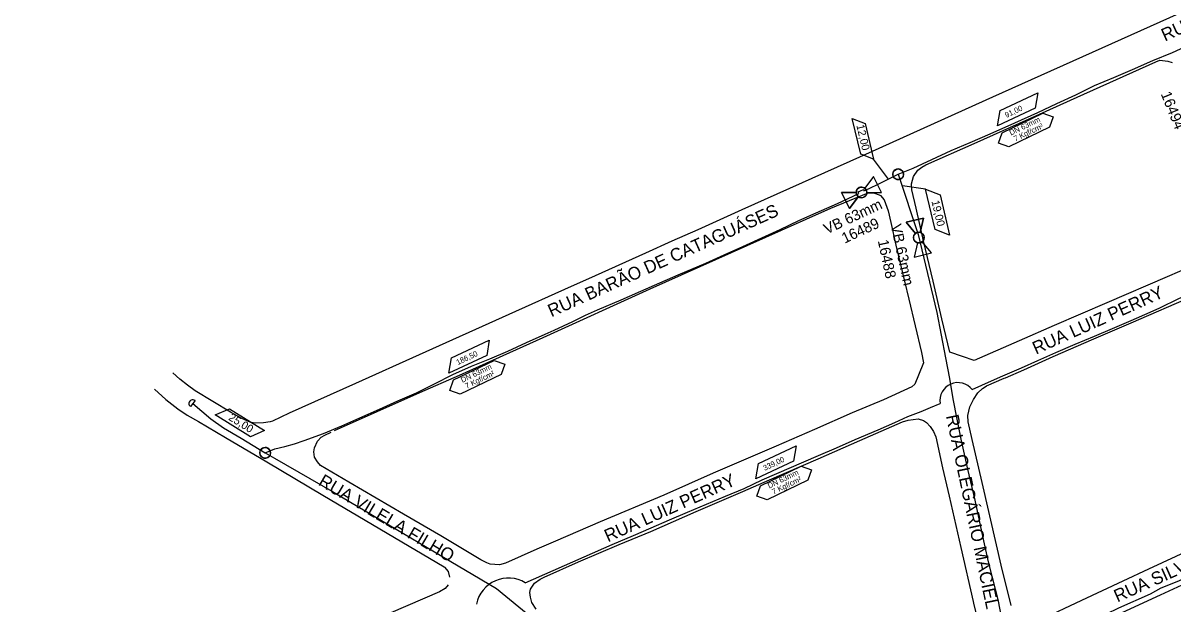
# Model space of a CAD drawing. Extents: x 656692 to 673945, y 7585994 to 7599066.
# Drawn here: x 668346 to 668995, y 7595131 to 7595459 of the extents above; entities that cross this region are included whole.
import ezdxf

# ---------------------------------------------------------------- set-up
doc = ezdxf.new("R2010")
doc.units = 0
for name, color, linetype in [('LOGRADOURO', 7, 'Continuous'), ('LOGRADOURO_TEXTO', 7, 'Continuous'), ('SIMBOLO', 7, 'Continuous'), ('TEXTO', 7, 'Continuous'), ('TUBO_PEAD_GN_63', 7, 'Continuous'), ('VALVULA_PEAD_63', 7, 'Continuous')]:
    doc.layers.add(name, color=color, linetype=linetype)

# ---------------------------------------------------------------- blocks, each defined once
blk = doc.blocks.new('VALVULA_PEAD_DN_16')
at = {"layer": 'VALVULA_PEAD_63'}
for points in [[(-0.0374, 0.0187), (-0.1395, 0.0698), (-0.1395, -0.0698), (-0.0374, -0.0187)], [(-0.0374, -0.0187), (-0.1395, -0.0698), (-0.1395, 0.0698), (-0.0374, 0.0187)], [(0.0374, -0.0187), (0.1395, -0.0698), (0.1395, 0.0698), (0.0374, 0.0187)], [(0.0374, -0.0187), (0.1395, -0.0698), (0.1395, 0.0698), (0.0374, 0.0187)]]:
    blk.add_lwpolyline(points, dxfattribs=at)
blk.add_circle((0, 0), 0.0419, dxfattribs=at)
for start, end in [(90, 270), (153.43495, 206.56505), (270, 90), (333.43495, 26.56505)]:
    blk.add_arc((0, 0), 0.0419, start, end, dxfattribs=at)
blk = doc.blocks.new('INTERLIGACAO_9')
at = {"layer": 'SIMBOLO'}
blk.add_circle((0, 0), 4.19, dxfattribs=at)
for start, end in [(0, 180), (180, 0)]:
    blk.add_arc((0, 0), 4.19, start, end, dxfattribs=at)

msp = doc.modelspace()

# ---------------------------------------------------------------- linework, layer by layer
at = {"layer": 'LOGRADOURO'}
for points in [[(669095.2, 7595507.7), (668966.3, 7595449.79), (668893.69, 7595417.16), (668825.71, 7595386.62), (668752.03, 7595353.68), (668727.27, 7595342.48), (668712.54, 7595335.94), (668697.66, 7595329.3), (668665.49, 7595314.85), (668655.65, 7595310.4), (668620.5, 7595294.72), (668569.88, 7595271.98), (668533.87, 7595255.79), (668496.45, 7595239.02), (668486.96, 7595234.51), (668485.66, 7595234.05), (668481.99, 7595233.54), (668477.36, 7595233.36), (668474.76, 7595233.65), (668469.68, 7595235.96), (668463.28, 7595239.51), (668443.29, 7595251.52), (668439, 7595254.73), (668434.77, 7595258.09), (668430.81, 7595261.82)], [(669013.1, 7595324.83), (668992.3, 7595315.82), (668958.18, 7595301.17), (668928.49, 7595288.41), (668908.71, 7595279.71), (668883.26, 7595268.7), (668876.62, 7595270.96), (668869.59, 7595273.35), (668865.06, 7595292.18), (668860.14, 7595313.52), (668854.66, 7595336.27), (668850.43, 7595354.61), (668848.11, 7595364.89), (668847.92, 7595368.35), (668848.97, 7595372.5), (668851.47, 7595376.04), (668853.69, 7595377.77), (668855.93, 7595379.08), (668883.16, 7595391.12), (668914.22, 7595405.05), (668941.38, 7595417.28), (668985.8, 7595437.14), (668988.02, 7595438.05), (668992.52, 7595437.56), (668995.03, 7595436.8)], [(668829.51, 7595362.24), (668830.43, 7595361.7), (668832.39, 7595359.31), (668834.67, 7595353.16), (668836.23, 7595346.52), (668839.07, 7595333.81), (668846.37, 7595303.29), (668853.42, 7595273.26), (668854.71, 7595267.4), (668851.88, 7595260.5), (668849.76, 7595255.28), (668848.05, 7595253.75), (668832.05, 7595246.5), (668814.39, 7595239.11), (668793.16, 7595229.81), (668771.48, 7595220.34), (668735.79, 7595205.11), (668708.02, 7595192.68), (668672.1, 7595177.61), (668646.92, 7595166.81), (668636.34, 7595162.21), (668618.61, 7595154.32), (668615.17, 7595153.51), (668610.02, 7595153.84), (668608, 7595154.59), (668604.64, 7595156.24), (668582.12, 7595169.71), (668561, 7595182.06), (668530.09, 7595200.09), (668514.15, 7595209.52), (668512.43, 7595211.51), (668510.78, 7595214.1), (668510.36, 7595217.12), (668510.71, 7595219.43), (668512.36, 7595223.22), (668514.5, 7595225.44), (668516.59, 7595226.65), (668520.18, 7595228.24)], [(668802.36, 7595354.63), (668823.4, 7595363.24), (668826.99, 7595363.17), (668829.51, 7595362.24)], [(668522.14, 7595229.12), (668570.28, 7595250.56), (668592.66, 7595260.39), (668639.85, 7595281.68), (668700.36, 7595309.18), (668746.28, 7595329.64), (668774.48, 7595342.15), (668802.36, 7595354.63)], [(668904.06, 7595130.54), (668898.51, 7595153.33), (668895.91, 7595164.68), (668887.82, 7595199.81), (668882.14, 7595224.07), (668879.84, 7595234.13), (668879.7, 7595237.73), (668880.81, 7595242.49), (668882.83, 7595246.73), (668885.29, 7595250.42), (668887.9, 7595252.93), (668889.45, 7595253.87), (668890.18, 7595254.32), (668900.17, 7595258.78), (668901.03, 7595259.01), (668911.32, 7595263.45), (668927.81, 7595270.9), (668950.83, 7595280.89), (668971.82, 7595289.9), (669007.48, 7595305.37)], [(668420.49, 7595252.56), (668426.74, 7595246.74), (668433.65, 7595241.39), (668438.9, 7595237.79), (668445.27, 7595234.25), (668460.45, 7595225.28), (668483.83, 7595211.46), (668515.38, 7595192.72), (668583.94, 7595152.26), (668584.21, 7595152.13), (668586.25, 7595149.68), (668587.01, 7595146.45)], [(668635.95, 7595128.47), (668633.45, 7595132.15), (668632.65, 7595135.22), (668632.27, 7595137.86), (668632.8, 7595139.77), (668635, 7595143.09), (668638.2, 7595145.41), (668640.5, 7595146.52), (668659.83, 7595155.09), (668682.73, 7595164.9), (668700.58, 7595172.24), (668726.33, 7595183.43), (668752.68, 7595194.84), (668767.65, 7595201.45), (668795.24, 7595213.32), (668818.64, 7595223.65), (668842.79, 7595234.13), (668845.93, 7595235.05), (668851.64, 7595235.83), (668854.67, 7595234.87), (668856.4, 7595233.69), (668858.45, 7595231.55), (668860.29, 7595228.62), (668861.53, 7595225.55), (668865.45, 7595208.13), (668869.1, 7595192.21), (668875.78, 7595163.23), (668882.69, 7595132.81), (668882.94, 7595131.72), (668885.16, 7595122.52)], [(669004.76, 7595161.75), (668981.67, 7595150.9), (668967.21, 7595144.22), (668943.82, 7595133.25), (668920.73, 7595122.42)], [(668925.27, 7595107.28), (668988.53, 7595136.48), (669015.31, 7595149)], [(668586.17, 7595142.17), (668584.61, 7595140.11), (668581.34, 7595138.22), (668526.44, 7595114.47), (668496.18, 7595101.48), (668451.14, 7595081.88), (668416.13, 7595066.8), (668395.98, 7595058.02), (668377.86, 7595050.28), (668373.21, 7595049.71), (668368.41, 7595050.52), (668367.4, 7595050.88), (668364.76, 7595052.52), (668361.54, 7595055.64), (668359.18, 7595059.46), (668353.9, 7595071.87), (668346.14, 7595089.62)]]:
    msp.add_lwpolyline(points, dxfattribs=at)
at = {"layer": 'SIMBOLO'}
for points in [[(668896.95, 7595391.28), (668899.02, 7595397.18), (668922.04, 7595408.24), (668927.94, 7595406.17), (668925.87, 7595400.26), (668902.85, 7595389.21), (668896.95, 7595391.28)], [(668587.19, 7595251.82), (668589.26, 7595257.73), (668612.28, 7595268.79), (668618.18, 7595266.71), (668616.11, 7595260.81), (668593.09, 7595249.75), (668587.19, 7595251.82)], [(668760.46, 7595192.16), (668762.53, 7595198.07), (668785.55, 7595209.12), (668791.45, 7595207.05), (668789.38, 7595201.15), (668766.36, 7595190.09), (668760.46, 7595192.16)]]:
    msp.add_lwpolyline(points, dxfattribs=at)
at = {"layer": 'TEXTO'}
for p, q in [((668834.84, 7595371.04), (668826.33, 7595382.3)), ((668855.85, 7595365.33), (668842.73, 7595367.22))]:
    msp.add_line(p, q, dxfattribs=at)
for points in [[(668897.91, 7595409.73), (668919.19, 7595419.7), (668917.78, 7595411.05), (668896.36, 7595401.03), (668897.91, 7595409.73)], [(668897.91, 7595409.73), (668919.19, 7595419.7), (668917.78, 7595411.05), (668896.36, 7595401.03), (668897.91, 7595409.73)], [(668821.63, 7595402.35), (668826.33, 7595382.3), (668819.17, 7595385.07), (668814.44, 7595405.24), (668821.63, 7595402.35)], [(668863.96, 7595362.07), (668869.26, 7595339.45), (668861.19, 7595342.58), (668855.85, 7595365.34), (668863.96, 7595362.07)], [(668863.96, 7595362.07), (668869.26, 7595339.45), (668861.19, 7595342.58), (668855.85, 7595365.33), (668863.96, 7595362.07)], [(668588.15, 7595270.28), (668609.43, 7595280.25), (668608.02, 7595271.6), (668586.6, 7595261.57), (668588.15, 7595270.28)], [(668588.15, 7595270.28), (668609.44, 7595280.25), (668608.02, 7595271.6), (668586.61, 7595261.57), (668588.15, 7595270.28)], [(668462.76, 7595241.39), (668482.5, 7595229.15), (668474.58, 7595225.65), (668454.72, 7595237.97), (668462.76, 7595241.39)], [(668462.76, 7595241.39), (668482.5, 7595229.15), (668474.58, 7595225.65), (668454.72, 7595237.96), (668462.76, 7595241.39)], [(668761.41, 7595210.62), (668782.7, 7595220.58), (668781.29, 7595211.94), (668759.87, 7595201.91), (668761.41, 7595210.62)], [(668761.42, 7595210.62), (668782.7, 7595220.58), (668781.29, 7595211.94), (668759.87, 7595201.91), (668761.42, 7595210.62)]]:
    msp.add_lwpolyline(points, dxfattribs=at)
at = {"layer": 'TUBO_PEAD_GN_63'}
msp.add_line((668443.28, 7595246.12), (668440.69, 7595242.71), dxfattribs=at)
for points in [[(668840.32, 7595373.73), (668840.36, 7595373.75), (668848.75, 7595377.25), (668859.32, 7595382.09), (668870.21, 7595387.08), (668880.98, 7595391.75), (668892.22, 7595396.65), (668906.3, 7595402.81), (668919.21, 7595408.53), (668929.89, 7595413.58), (668940.66, 7595418.62), (668951.23, 7595423.75), (668962.11, 7595428.32), (668972.67, 7595432.89), (668984.21, 7595437.92), (668995.22, 7595442.46), (669004.26, 7595446.49)], [(668819.12, 7595364.38), (668820.75, 7595365.07), (668821.02, 7595364.48), (668823.92, 7595365.81), (668829.36, 7595368.35), (668840.32, 7595373.73)], [(668840.36, 7595373.75), (668851.55, 7595339.81), (668862.24, 7595295.86), (668867.06, 7595270.12), (668869.3, 7595258.61), (668871.25, 7595247.01), (668873.42, 7595235.62), (668875.64, 7595224.28), (668879.52, 7595207.33), (668883.53, 7595189.9), (668885.99, 7595178.53), (668888.53, 7595166.92), (668891.21, 7595155.2), (668893.32, 7595146.36), (668896.59, 7595133.94), (668900, 7595116.3)], [(668482.92, 7595216.6), (668488.37, 7595218.89), (668493.95, 7595220.17), (668499.43, 7595221.7), (668504.95, 7595223.57), (668515.75, 7595227.45), (668526.27, 7595231.92), (668536.36, 7595236.41), (668547.54, 7595241.26), (668557.76, 7595246.02), (668568.43, 7595250.5), (668578.59, 7595255.51), (668588.92, 7595260.78), (668599.36, 7595265.42), (668609.8, 7595269.58), (668619.83, 7595274.02), (668630.49, 7595278.76), (668641.06, 7595283.56), (668646.17, 7595285.88), (668656.55, 7595290.65), (668663.85, 7595294.22), (668670.61, 7595297.21), (668683.98, 7595302.91), (668694.95, 7595307.81), (668705.67, 7595312.51), (668716.16, 7595317.07), (668731.81, 7595323.65), (668742.17, 7595328.35), (668752.59, 7595333.08), (668763.34, 7595337.83), (668773.64, 7595342.6), (668784.32, 7595347.6), (668794.1, 7595352), (668806.12, 7595357.19), (668818.09, 7595362.93), (668817.75, 7595363.81), (668819.12, 7595364.38)], [(668882.05, 7595252.26), (668887.54, 7595254.73), (668898.11, 7595259.44), (668910.02, 7595264.54), (668919.25, 7595268.72), (668929.43, 7595273.21), (668940.37, 7595277.91), (668951.11, 7595282.51), (668961.3, 7595286.76), (668971.88, 7595291.25), (668982.68, 7595296), (668988.03, 7595298.36), (668998.79, 7595303.61), (669008.5, 7595307.55), (669021.94, 7595313.31), (669028.08, 7595316.3)], [(668441.99, 7595244.41), (668452.31, 7595235.83), (668459.46, 7595230.75), (668469.33, 7595224.93), (668482.92, 7595216.6), (668488.09, 7595213.63), (668521.93, 7595194.25), (668613.55, 7595140.09), (668640.82, 7595117.7)], [(668629.75, 7595143.37), (668678.9, 7595164.84), (668690.97, 7595169.93), (668700.79, 7595174.24), (668711.24, 7595178.81), (668721.39, 7595183.13), (668732.11, 7595187.64), (668742.89, 7595192.08), (668753.32, 7595196.58), (668763.52, 7595201.34), (668795.27, 7595215.07), (668805.59, 7595219.44), (668815.96, 7595224.22), (668829.04, 7595229.54), (668838.54, 7595233.75), (668845.77, 7595237.06), (668853.41, 7595239.99), (668858.57, 7595242.16), (668864.05, 7595244.51)], [(668914.82, 7595106.62), (668918.25, 7595108.27), (668928.88, 7595112.72), (668939.67, 7595117.8), (668950.77, 7595122.84), (668957.9, 7595125.81), (668964.93, 7595129.21), (668982.74, 7595137.08), (668988.79, 7595140.45), (668998.84, 7595144.42), (669004.12, 7595147.09), (669015.63, 7595152.86), (669025.91, 7595157.37), (669035.74, 7595162.04), (669060.66, 7595173.55), (669064.75, 7595175.74)]]:
    msp.add_lwpolyline(points, dxfattribs=at)
for centre, radius, start, end in [((668874.02, 7595246.12), 10.1, 37.38716, 189.16835), ((668441.99, 7595244.41), 2.14, 52.75735, 232.75735), ((668620.24, 7595127.59), 18.42, 58.92453, 168.26767)]:
    msp.add_arc(centre, radius, start, end, dxfattribs=at)

# ---------------------------------------------------------------- block references
at = {"layer": 'SIMBOLO', "xscale": 0.7229249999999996, "yscale": 0.7229249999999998, "rotation": 166.312122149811}
for p in [(668840.31, 7595373.74), (668482.88, 7595216.59)]:
    msp.add_blockref('INTERLIGACAO_9', p, dxfattribs=at)
at = {"layer": 'VALVULA_PEAD_63', "xscale": 72.29249999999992}
for p, yscale, rotation in [((668819.64, 7595363.49), 72.29249999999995, 26.837976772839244), ((668851.98, 7595338.04), 72.29249999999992, -76.87523629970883)]:
    msp.add_blockref('VALVULA_PEAD_DN_16', p, dxfattribs=dict(at, yscale=yscale, rotation=rotation))

# ---------------------------------------------------------------- texts
for s, rotation, p in [('16494', 292.04801, (668988.51, 7595419.09)), ('VB 63mm', 25.04801, (668800.04, 7595339.78)), ('16489', 25.04801, (668810.13, 7595334.58)), ('VB 63mm', 282.04801, (668836.13, 7595344.93)), ('16488', 282.04801, (668828.79, 7595336.27))]:
    msp.add_text(s, height=6, rotation=rotation).set_placement(p)
at = {"layer": 'LOGRADOURO_TEXTO'}
for s, rotation, p in [('RUA BARÃO DE CATAGUÁSES', 24.30453, (668990.93, 7595448.6)), ('RUA BARÃO DE CATAGUÁSES', 24.08862, (668644.5, 7595293.05)), ('RUA LUIZ PERRY', 24.10472, (668918.14, 7595272)), ('RUA OLEGÁRIO MACIEL', 281.89425, (668867.22, 7595237.44)), ('RUA VILELA FILHO', 329.42064, (668512.43, 7595198.76)), ('RUA LUIZ PERRY', 24.10472, (668676.42, 7595166.09)), ('RUA SILVA JARDIM', 24.10472, (668964.13, 7595132.15))]:
    msp.add_text(s, height=7.2, rotation=rotation, dxfattribs=at).set_placement(p)
at = {"layer": 'TEXTO'}
for s, height, rotation, p in [('91,00', 3.113, 25.08912, (668901.46, 7595405.54)), ('DN 63mm', 3.113, 25.66002, (668904.03, 7595395.54)), ('12,00', 4.447, 283.19761, (668816.7, 7595401.34)), ('7 Kgf/cm²', 3.113, 25.66002, (668906.47, 7595392.13)), ('19,00', 4.447, 283.19762, (668859.11, 7595358.53)), ('186,50', 3.113, 25.08912, (668591.7, 7595266.08)), ('DN 63mm', 3.113, 25.66002, (668594.27, 7595256.08)), ('7 Kgf/cm²', 3.113, 25.66002, (668596.71, 7595252.68)), ('25,00', 4.447, 328.19762, (668461.84, 7595235.46)), ('339,00', 3.113, 25.08912, (668764.97, 7595206.42)), ('DN 63mm', 3.113, 25.66002, (668767.54, 7595196.42)), ('7 Kgf/cm²', 3.113, 25.66002, (668769.98, 7595193.02))]:
    msp.add_text(s, height=height, rotation=rotation, dxfattribs=at).set_placement(p)

doc.saveas('drawing.dxf')
